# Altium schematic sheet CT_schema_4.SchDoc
size 421 x 351 mm
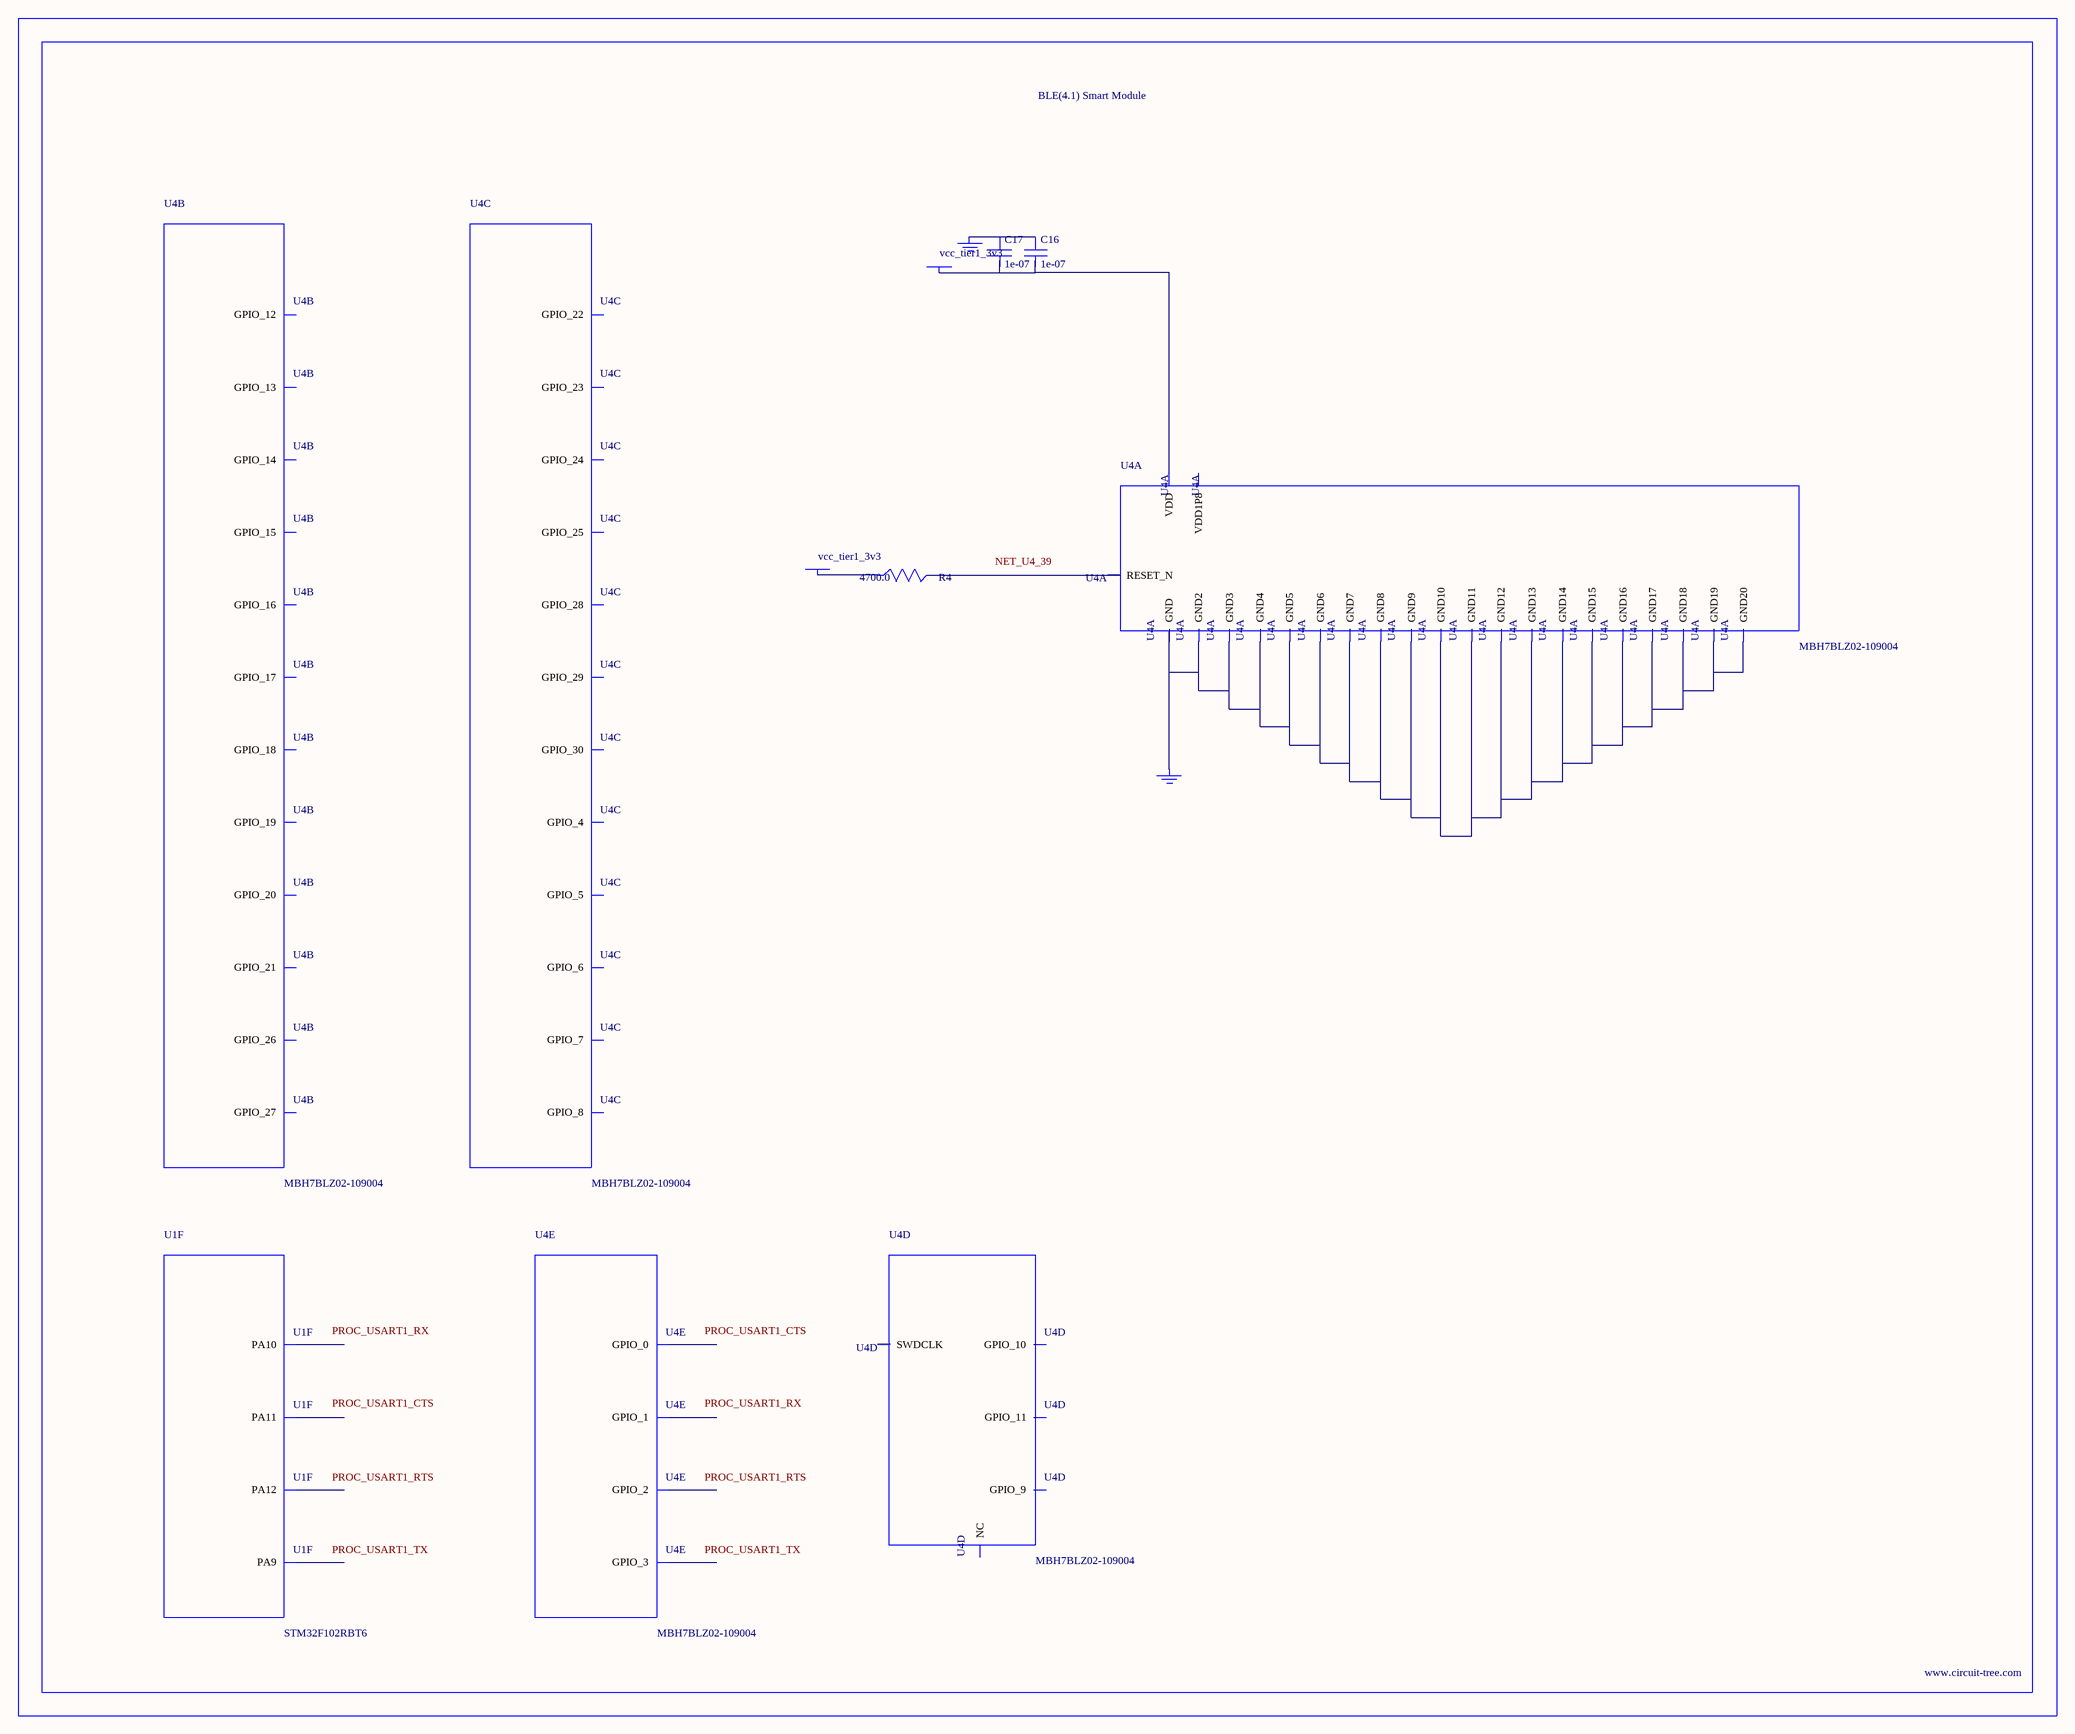
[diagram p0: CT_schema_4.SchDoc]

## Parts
BORDER3  (no value)
C16  1e-07  [C0402]
C17  1e-07  [C0402]
GND_INSTANCE_3_0  (no value)
GND_INSTANCE_3_1  (no value)
POWER_INSTANCE_3_0  vcc_tier1_3v3
POWER_INSTANCE_3_1  vcc_tier1_3v3
R4  4700.0  [R0603]
U1  STM32F102RBT6  [LQFP64]  (part F of 7)
U4  MBH7BLZ02-109004  [MBH7BLZ02-109004]  (parts A,B,C,D,E of 5)

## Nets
NetC16_1: C16.1 C17.1 GND_INSTANCE_3_0.0(GND)
NetC16_2: C16.2 C17.2 POWER_INSTANCE_3_0.0(PWR) U4.28(VDD)
NetGND_INSTANCE_3_1_0: GND_INSTANCE_3_1.0(GND) U4.1(GND) U4.3(GND2) U4.15(GND3) U4.27(GND4) U4.29(GND5) U4.41(GND6) U4.42(GND7) U4.43(GND8) U4.44(GND9) U4.45(GND10) U4.46(GND11) U4.47(GND12) U4.48(GND13) U4.49(GND14) U4.50(GND15) U4.52(GND16) U4.53(GND17) U4.54(GND18) U4.55(GND19) U4.56(GND20)
NetPOWER_INSTANCE_3_1_0: POWER_INSTANCE_3_1.0(PWR) R4.1
NetR4_2: R4.2 U4.39(RESET_N)

Not connected (* = marked no-connect by the designer): U1 42(PA9) 43(PA10) 44(PA11) 45(PA12); U4 2(VDD1P8) 4(GPIO_17) 5(GPIO_19) 6(GPIO_18) 7(GPIO_20) 8(GPIO_16) 9(GPIO_15) 10(GPIO_14) 11(GPIO_13) 12(GPIO_12) 13(GPIO_27) 14(GPIO_26) 16(GPIO_21) 17(GPIO_22) 18(GPIO_23) 19(GPIO_24) 20(GPIO_6) 21(GPIO_5) 22(GPIO_4) 23(GPIO_3) 24(GPIO_2) 25(GPIO_1) 26(GPIO_0) 30(GPIO_25) 31(GPIO_29) 32(GPIO_28) 33(GPIO_30) 34(GPIO_7) 35(GPIO_8) 36(GPIO_9) 37(GPIO_10) 38(GPIO_11) 40(SWDCLK) 51(NC)

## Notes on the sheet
- Labels drawn without touching a wire or pin: NET_U4_39, PROC_USART1_CTS, PROC_USART1_RTS, PROC_USART1_RX, PROC_USART1_TX

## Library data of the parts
BORDER3 = BORDER_PAGE3
C16 C17 = C0402C104K3RACTU
GND_INSTANCE_3_0 GND_INSTANCE_3_1 = GND
POWER_INSTANCE_3_0 POWER_INSTANCE_3_1 = PWR
R4 = RC0603JR-074K7L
